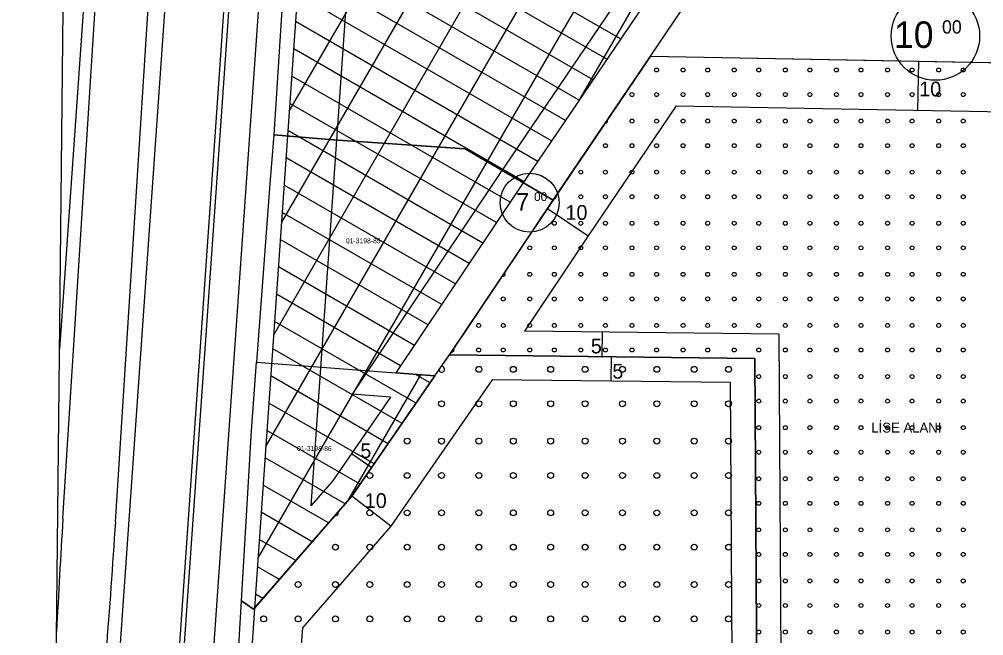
# Model space of a CAD drawing. Extents: x 419396 to 421519, y 4453567 to 4456767.
# Drawn here: x 420195.1 to 420391.3, y 4455033.3 to 4455158.8 of the extents above; entities that cross this region are included whole.
import ezdxf

# ---------------------------------------------------------------- set-up
doc = ezdxf.new("R2010")
doc.units = 0
for name, color, linetype in [('0_KADASTRO', 7, 'Continuous'), ('@PL', 7, 'Continuous'), ('ADAKENARI1000', 7, 'Continuous'), ('DEGISIKLIK_PARSELNO', 7, 'Continuous'), ('F_YAPI_YAKLAŞMA', 7, 'Continuous'), ('FAT_RAYLıSISTEM', 7, 'Continuous'), ('KALDIRIM', 7, 'Continuous'), ('Level 35', 7, 'Continuous'), ('Level 43', 7, 'Continuous'), ('Y_Lejant', 7, 'Continuous')]:
    doc.layers.add(name, color=color, linetype=linetype)

msp = doc.modelspace()

# ---------------------------------------------------------------- linework, layer by layer
at = {"layer": '0_KADASTRO'}
for p, q in [((420323.5, 4455151.27), (420340.02, 4455175.71)), ((420246.85, 4455135.3), (420246.05, 4455125.31)), ((420285.83, 4455132.45), (420303.7, 4455121.98)), ((420246.05, 4455125.31), (420243.35, 4455089.04)), ((420300.77, 4455117.6), (420300.9, 4455117.8)), ((420279.66, 4455086.21), (420282.64, 4455090.54)), ((420243.35, 4455089.04), (420279.66, 4455086.21))]:
    msp.add_line(p, q, dxfattribs=at)
for points in [[(420293.99, 4455228.12), (420291.73, 4455205.79), (420252.3, 4455209.37), (420248.66, 4455162.87), (420246.85, 4455135.3)], [(420303.7, 4455121.98), (420304.63, 4455123.36), (420323.5, 4455151.27)], [(420246.85, 4455135.3), (420255.73, 4455134.55), (420259.96, 4455134.2), (420274.95, 4455133.19), (420285.83, 4455132.45)], [(420274.95, 4455133.19), (420259.96, 4455134.2), (420255.73, 4455134.55), (420246.85, 4455135.3)], [(420300.9, 4455117.8), (420302.55, 4455120.28), (420303.7, 4455121.98), (420285.83, 4455132.45), (420274.95, 4455133.19)], [(420282.64, 4455090.54), (420297, 4455111.92), (420298.13, 4455113.63), (420300.77, 4455117.6)]]:
    msp.add_lwpolyline(points, dxfattribs=at)
for points in [[(420282.64, 4455090.54), (420297, 4455111.92), (420302.55, 4455120.28), (420304.63, 4455123.36), (420323.5, 4455151.27), (420436.44, 4455149.21), (420436.45, 4455145.33), (420439.36, 4455123.19), (420445.76, 4455074.56), (420468.34, 4454994.88), (420469.12, 4454986.67), (420468.62, 4454979.78), (420466.97, 4454973.08), (420464.21, 4454966.74), (420458.28, 4454957.65), (420451.94, 4454952.12), (420444.92, 4454948.04), (420432.46, 4454945.39), (420391.72, 4454939.02), (420368.62, 4454935.68), (420345.72, 4454934.33), (420344.76, 4455089.79)], [(420235.11, 4454952.64), (420240.31, 4455040.41), (420242.76, 4455038.75), (420262.76, 4455061.76), (420279.66, 4455086.21), (420281.91, 4455089.46), (420282.64, 4455090.54), (420344.76, 4455089.79), (420345.72, 4454934.33), (420272.67, 4454930.03), (420267.59, 4454930.12), (420261.9, 4454931.28), (420257.42, 4454932.55), (420253.39, 4454934.03), (420249.93, 4454935.75), (420245.65, 4454938.18), (420242, 4454941), (420237.77, 4454944.85), (420235.41, 4454949.09)], [(420240.31, 4455040.41), (420242.31, 4455075.03), (420243.35, 4455089.04), (420279.66, 4455086.21), (420262.76, 4455061.76), (420242.76, 4455038.75)]]:
    msp.add_lwpolyline(points, close=True, dxfattribs=at)
at = {"layer": '@PL'}
for centre, radius in [((420381.48, 4455155.39), 9), ((420298.93, 4455121.46), 6)]:
    msp.add_circle(centre, radius, dxfattribs=at)
at = {"layer": 'ADAKENARI1000'}
for p, q in [((420265.69, 4455363.64), (420242.95, 4455038.97)), ((420323.63, 4455163.96), (420296.75, 4455124.2)), ((420323.5, 4455151.27), (420302.56, 4455120.29)), ((420323.5, 4455151.27), (420436.44, 4455149.21)), ((420296.75, 4455124.2), (420271.71, 4455086.83)), ((420302.56, 4455120.29), (420282.62, 4455090.54)), ((420279.66, 4455086.21), (420282.62, 4455090.54)), ((420344.76, 4455089.79), (420282.62, 4455090.54)), ((420345.72, 4454934.33), (420344.76, 4455089.79)), ((420279.66, 4455086.21), (420271.71, 4455086.83)), ((420279.66, 4455086.21), (420262.76, 4455061.76)), ((420262.76, 4455061.76), (420242.95, 4455038.97)), ((420242.95, 4455038.97), (420241.29, 4455015.25))]:
    msp.add_line(p, q, dxfattribs=at)
at = {"layer": 'F_YAPI_YAKLAŞMA'}
for p, q in [((420318.89, 4455165.89), (420292.6, 4455126.99)), ((420377.94, 4455140.27), (420378.13, 4455150.27)), ((420328.74, 4455141.17), (420310.86, 4455114.71)), ((420328.74, 4455141.17), (420427.14, 4455139.38)), ((420292.6, 4455126.99), (420262.8, 4455082.51)), ((420302.56, 4455120.29), (420310.87, 4455114.72)), ((420310.86, 4455114.71), (420297.89, 4455095.36)), ((420349.73, 4455094.73), (420297.89, 4455095.36)), ((420313.69, 4455090.17), (420313.75, 4455095.17)), ((420350.66, 4454944.64), (420349.73, 4455094.73)), ((420315.54, 4455085.15), (420315.6, 4455090.14)), ((420291.28, 4455085.44), (420270.67, 4455055.62)), ((420339.79, 4455084.85), (420291.28, 4455085.44)), ((420340.66, 4454944.05), (420339.79, 4455084.85)), ((420270.6, 4455081.9), (420262.8, 4455082.51)), ((420270.6, 4455081.9), (420258.8, 4455064.83)), ((420262.69, 4455070.45), (420266.8, 4455067.61)), ((420258.8, 4455064.83), (420254.43, 4455059.8)), ((420270.67, 4455055.62), (420262.76, 4455061.76)), ((420270.67, 4455055.62), (420252.69, 4455034.93)), ((420252.69, 4455034.93), (420251.27, 4455014.64))]:
    msp.add_line(p, q, dxfattribs=at)
msp.add_lwpolyline([(420275.71, 4455363.6), (420254.43, 4455059.8)], dxfattribs=at)
at = {"layer": 'FAT_RAYLıSISTEM'}
for p, q in [((420214.7, 4455056.5), (420222.56, 4455180.73)), ((420203.96, 4455057.18), (420211.66, 4455178.85))]:
    msp.add_line(p, q, dxfattribs=at)
for centre, start, end in [((421800.78, 4454956.24), 176.38298, 177.20849), ((418617.89, 4455157.44), 354.48143, 356.38298)]:
    msp.add_arc(centre, 1600, start, end, dxfattribs=at)
at = {"layer": 'KALDIRIM'}
for p, q in [((420234.65, 4455539.59), (420203.28, 4455091.64)), ((420251.12, 4455538.54), (420214.59, 4455016.89)), ((420263.1, 4455537.78), (420226.57, 4455016.15)), ((420264.1, 4455537.72), (420227.56, 4455016.09)), ((420258.38, 4455370.29), (420233.55, 4455015.72))]:
    msp.add_line(p, q, dxfattribs=at)
at = {"layer": 'Level 35'}
for p, q in [((420250.03, 4455140.11), (420360.82, 4455331.99)), ((420248.44, 4455117.35), (420370.12, 4455328.11)), ((420246.85, 4455094.59), (420340.18, 4455256.25)), ((420245.25, 4455071.83), (420334.89, 4455227.09)), ((420243.66, 4455049.07), (420329.73, 4455198.15)), ((420317.44, 4455154.81), (420253.64, 4455191.64)), ((420314.64, 4455150.66), (420253.25, 4455186.09)), ((420311.83, 4455146.5), (420252.87, 4455180.55)), ((420309.02, 4455142.35), (420252.48, 4455175)), ((420306.21, 4455138.2), (420252.09, 4455169.45)), ((420309.3, 4455142.77), (420324.57, 4455169.2)), ((420303.41, 4455134.04), (420251.7, 4455163.9)), ((420300.6, 4455129.89), (420251.31, 4455158.35)), ((420297.79, 4455125.74), (420250.92, 4455152.8)), ((420295, 4455121.58), (420250.53, 4455147.25)), ((420292.21, 4455117.42), (420250.14, 4455141.7)), ((420289.42, 4455113.25), (420249.76, 4455136.15)), ((420286.63, 4455109.09), (420249.37, 4455130.6)), ((420283.84, 4455104.93), (420248.98, 4455125.05)), ((420281.05, 4455100.77), (420248.59, 4455119.51)), ((420278.26, 4455096.6), (420248.2, 4455113.96)), ((420275.47, 4455092.44), (420247.81, 4455108.41)), ((420272.68, 4455088.28), (420247.42, 4455102.86)), ((420275.84, 4455080.68), (420247.04, 4455097.31)), ((420272.99, 4455076.55), (420246.65, 4455091.76)), ((420262.08, 4455060.98), (420276.78, 4455086.43)), ((420278.69, 4455084.81), (420275.73, 4455086.52)), ((420270.13, 4455072.43), (420246.26, 4455086.21)), ((420267.28, 4455068.3), (420245.87, 4455080.66)), ((420264.43, 4455064.17), (420245.48, 4455075.11)), ((420261.37, 4455060.16), (420245.09, 4455069.56)), ((420258.03, 4455056.32), (420244.7, 4455064.01)), ((420254.69, 4455052.48), (420244.32, 4455058.46)), ((420251.35, 4455048.63), (420243.93, 4455052.92)), ((420248.01, 4455044.79), (420243.54, 4455047.37)), ((420244.67, 4455040.94), (420243.15, 4455041.82))]:
    msp.add_line(p, q, dxfattribs=at)
at = {"layer": 'Level 43'}
for centre, radius in [((420324.75, 4455148.49), 0.4), ((420330.15, 4455148.49), 0.4), ((420335.15, 4455148.49), 0.4), ((420340.55, 4455148.49), 0.4), ((420345.55, 4455148.49), 0.4), ((420350.95, 4455148.49), 0.4), ((420355.95, 4455148.49), 0.4), ((420361.35, 4455148.49), 0.4), ((420366.35, 4455148.49), 0.4), ((420371.75, 4455148.49), 0.4), ((420376.75, 4455148.49), 0.4), ((420382.15, 4455148.49), 0.4), ((420387.15, 4455148.49), 0.4), ((420319.75, 4455143.49), 0.4), ((420324.75, 4455143.49), 0.4), ((420330.15, 4455143.49), 0.4), ((420335.15, 4455143.49), 0.4), ((420340.55, 4455143.49), 0.4), ((420345.55, 4455143.49), 0.4), ((420350.95, 4455143.49), 0.4), ((420355.95, 4455143.49), 0.4), ((420361.35, 4455143.49), 0.4), ((420366.35, 4455143.49), 0.4), ((420371.75, 4455143.49), 0.4), ((420376.75, 4455143.49), 0.4), ((420382.15, 4455143.49), 0.4), ((420387.15, 4455143.49), 0.4), ((420319.75, 4455138.09), 0.4), ((420324.75, 4455138.09), 0.4), ((420330.15, 4455138.09), 0.4), ((420335.15, 4455138.09), 0.4), ((420340.55, 4455138.09), 0.4), ((420345.55, 4455138.09), 0.4), ((420350.95, 4455138.09), 0.4), ((420355.95, 4455138.09), 0.4), ((420361.35, 4455138.09), 0.4), ((420366.35, 4455138.09), 0.4), ((420371.75, 4455138.09), 0.4), ((420376.75, 4455138.09), 0.4), ((420382.15, 4455138.09), 0.4), ((420387.15, 4455138.09), 0.4), ((420314.35, 4455133.09), 0.4), ((420319.75, 4455133.09), 0.4), ((420324.75, 4455133.09), 0.4), ((420330.15, 4455133.09), 0.4), ((420335.15, 4455133.09), 0.4), ((420340.55, 4455133.09), 0.4), ((420345.55, 4455133.09), 0.4), ((420350.95, 4455133.09), 0.4), ((420355.95, 4455133.09), 0.4), ((420361.35, 4455133.09), 0.4), ((420366.35, 4455133.09), 0.4), ((420371.75, 4455133.09), 0.4), ((420376.75, 4455133.09), 0.4), ((420382.15, 4455133.09), 0.4), ((420387.15, 4455133.09), 0.4), ((420309.35, 4455127.69), 0.4), ((420314.35, 4455127.69), 0.4), ((420319.75, 4455127.69), 0.4), ((420324.75, 4455127.69), 0.4), ((420330.15, 4455127.69), 0.4), ((420335.15, 4455127.69), 0.4), ((420340.55, 4455127.69), 0.4), ((420345.55, 4455127.69), 0.4), ((420350.95, 4455127.69), 0.4), ((420355.95, 4455127.69), 0.4), ((420361.35, 4455127.69), 0.4), ((420366.35, 4455127.69), 0.4), ((420371.75, 4455127.69), 0.4), ((420376.75, 4455127.69), 0.4), ((420382.15, 4455127.69), 0.4), ((420387.15, 4455127.69), 0.4), ((420309.35, 4455122.69), 0.4), ((420314.35, 4455122.69), 0.4), ((420319.75, 4455122.69), 0.4), ((420324.75, 4455122.69), 0.4), ((420330.15, 4455122.69), 0.4), ((420335.15, 4455122.69), 0.4), ((420340.55, 4455122.69), 0.4), ((420345.55, 4455122.69), 0.4), ((420350.95, 4455122.69), 0.4), ((420355.95, 4455122.69), 0.4), ((420361.35, 4455122.69), 0.4), ((420366.35, 4455122.69), 0.4), ((420371.75, 4455122.69), 0.4), ((420376.75, 4455122.69), 0.4), ((420382.15, 4455122.69), 0.4), ((420387.15, 4455122.69), 0.4), ((420303.95, 4455117.29), 0.4), ((420309.35, 4455117.29), 0.4), ((420314.35, 4455117.29), 0.4), ((420319.75, 4455117.29), 0.4), ((420324.75, 4455117.29), 0.4), ((420330.15, 4455117.29), 0.4), ((420335.15, 4455117.29), 0.4), ((420340.55, 4455117.29), 0.4), ((420345.55, 4455117.29), 0.4), ((420350.95, 4455117.29), 0.4), ((420355.95, 4455117.29), 0.4), ((420361.35, 4455117.29), 0.4), ((420366.35, 4455117.29), 0.4), ((420371.75, 4455117.29), 0.4), ((420376.75, 4455117.29), 0.4), ((420382.15, 4455117.29), 0.4), ((420387.15, 4455117.29), 0.4), ((420298.95, 4455112.29), 0.4), ((420303.95, 4455112.29), 0.4), ((420309.35, 4455112.29), 0.4), ((420314.35, 4455112.29), 0.4), ((420319.75, 4455112.29), 0.4), ((420324.75, 4455112.29), 0.4), ((420330.15, 4455112.29), 0.4), ((420335.15, 4455112.29), 0.4), ((420340.55, 4455112.29), 0.4), ((420345.55, 4455112.29), 0.4), ((420350.95, 4455112.29), 0.4), ((420355.95, 4455112.29), 0.4), ((420361.35, 4455112.29), 0.4), ((420366.35, 4455112.29), 0.4), ((420371.75, 4455112.29), 0.4), ((420376.75, 4455112.29), 0.4), ((420382.15, 4455112.29), 0.4), ((420387.15, 4455112.29), 0.4), ((420298.95, 4455106.89), 0.4), ((420303.95, 4455106.89), 0.4), ((420309.35, 4455106.89), 0.4), ((420314.35, 4455106.89), 0.4), ((420319.75, 4455106.89), 0.4), ((420324.75, 4455106.89), 0.4), ((420330.15, 4455106.89), 0.4), ((420335.15, 4455106.89), 0.4), ((420340.55, 4455106.89), 0.4), ((420345.55, 4455106.89), 0.4), ((420350.95, 4455106.89), 0.4), ((420355.95, 4455106.89), 0.4), ((420361.35, 4455106.89), 0.4), ((420366.35, 4455106.89), 0.4), ((420371.75, 4455106.89), 0.4), ((420376.75, 4455106.89), 0.4), ((420382.15, 4455106.89), 0.4), ((420387.15, 4455106.89), 0.4), ((420293.55, 4455101.89), 0.4), ((420298.95, 4455101.89), 0.4), ((420303.95, 4455101.89), 0.4), ((420309.35, 4455101.89), 0.4), ((420314.35, 4455101.89), 0.4), ((420319.75, 4455101.89), 0.4), ((420324.75, 4455101.89), 0.4), ((420330.15, 4455101.89), 0.4), ((420335.15, 4455101.89), 0.4), ((420340.55, 4455101.89), 0.4), ((420345.55, 4455101.89), 0.4), ((420350.95, 4455101.89), 0.4), ((420355.95, 4455101.89), 0.4), ((420361.35, 4455101.89), 0.4), ((420366.35, 4455101.89), 0.4), ((420371.75, 4455101.89), 0.4), ((420376.75, 4455101.89), 0.4), ((420382.15, 4455101.89), 0.4), ((420387.15, 4455101.89), 0.4), ((420288.55, 4455096.49), 0.4), ((420293.55, 4455096.49), 0.4), ((420298.95, 4455096.49), 0.4), ((420303.95, 4455096.49), 0.4), ((420309.35, 4455096.49), 0.4), ((420314.35, 4455096.49), 0.4), ((420319.75, 4455096.49), 0.4), ((420324.75, 4455096.49), 0.4), ((420330.15, 4455096.49), 0.4), ((420335.15, 4455096.49), 0.4), ((420340.55, 4455096.49), 0.4), ((420345.55, 4455096.49), 0.4), ((420350.95, 4455096.49), 0.4), ((420355.95, 4455096.49), 0.4), ((420361.35, 4455096.49), 0.4), ((420366.35, 4455096.49), 0.4), ((420371.75, 4455096.49), 0.4), ((420376.75, 4455096.49), 0.4), ((420382.15, 4455096.49), 0.4), ((420387.15, 4455096.49), 0.4), ((420288.55, 4455091.49), 0.4), ((420293.55, 4455091.49), 0.4), ((420298.95, 4455091.49), 0.4), ((420303.95, 4455091.49), 0.4), ((420309.35, 4455091.49), 0.4), ((420314.35, 4455091.49), 0.4), ((420319.75, 4455091.49), 0.4), ((420324.75, 4455091.49), 0.4), ((420330.15, 4455091.49), 0.4), ((420335.15, 4455091.49), 0.4), ((420340.55, 4455091.49), 0.4), ((420345.55, 4455091.49), 0.4), ((420350.95, 4455091.49), 0.4), ((420355.95, 4455091.49), 0.4), ((420361.35, 4455091.49), 0.4), ((420366.35, 4455091.49), 0.4), ((420371.75, 4455091.49), 0.4), ((420376.75, 4455091.49), 0.4), ((420382.15, 4455091.49), 0.4), ((420387.15, 4455091.49), 0.4), ((420288.61, 4455087.56), 0.6), ((420295.61, 4455087.56), 0.6), ((420303.21, 4455087.56), 0.6), ((420310.21, 4455087.56), 0.6), ((420317.81, 4455087.56), 0.6), ((420324.81, 4455087.56), 0.6), ((420332.41, 4455087.56), 0.6), ((420339.41, 4455087.56), 0.6), ((420345.55, 4455086.09), 0.4), ((420350.95, 4455086.09), 0.4), ((420355.95, 4455086.09), 0.4), ((420361.35, 4455086.09), 0.4), ((420366.35, 4455086.09), 0.4), ((420371.75, 4455086.09), 0.4), ((420376.75, 4455086.09), 0.4), ((420382.15, 4455086.09), 0.4), ((420387.15, 4455086.09), 0.4), ((420281.01, 4455080.56), 0.6), ((420288.61, 4455080.56), 0.6), ((420295.61, 4455080.56), 0.6), ((420303.21, 4455080.56), 0.6), ((420310.21, 4455080.56), 0.6), ((420317.81, 4455080.56), 0.6), ((420324.81, 4455080.56), 0.6), ((420332.41, 4455080.56), 0.6), ((420339.41, 4455080.56), 0.6), ((420345.55, 4455081.09), 0.4), ((420350.95, 4455081.09), 0.4), ((420355.95, 4455081.09), 0.4), ((420361.35, 4455081.09), 0.4), ((420366.35, 4455081.09), 0.4), ((420371.75, 4455081.09), 0.4), ((420376.75, 4455081.09), 0.4), ((420382.15, 4455081.09), 0.4), ((420387.15, 4455081.09), 0.4), ((420345.55, 4455075.69), 0.4), ((420350.95, 4455075.69), 0.4), ((420355.95, 4455075.69), 0.4), ((420361.35, 4455075.69), 0.4), ((420366.35, 4455075.69), 0.4), ((420371.75, 4455075.69), 0.4), ((420376.75, 4455075.69), 0.4), ((420382.15, 4455075.69), 0.4), ((420387.15, 4455075.69), 0.4), ((420274.01, 4455072.96), 0.6), ((420281.01, 4455072.96), 0.6), ((420288.61, 4455072.96), 0.6), ((420295.61, 4455072.96), 0.6), ((420303.21, 4455072.96), 0.6), ((420310.21, 4455072.96), 0.6), ((420317.81, 4455072.96), 0.6), ((420324.81, 4455072.96), 0.6), ((420332.41, 4455072.96), 0.6), ((420339.41, 4455072.96), 0.6), ((420345.55, 4455070.69), 0.4), ((420350.95, 4455070.69), 0.4), ((420355.95, 4455070.69), 0.4), ((420361.35, 4455070.69), 0.4), ((420366.35, 4455070.69), 0.4), ((420371.75, 4455070.69), 0.4), ((420376.75, 4455070.69), 0.4), ((420382.15, 4455070.69), 0.4), ((420387.15, 4455070.69), 0.4), ((420266.41, 4455065.96), 0.6), ((420274.01, 4455065.96), 0.6), ((420281.01, 4455065.96), 0.6), ((420288.61, 4455065.96), 0.6), ((420295.61, 4455065.96), 0.6), ((420303.21, 4455065.96), 0.6), ((420310.21, 4455065.96), 0.6), ((420317.81, 4455065.96), 0.6), ((420324.81, 4455065.96), 0.6), ((420332.41, 4455065.96), 0.6), ((420339.41, 4455065.96), 0.6), ((420345.55, 4455065.29), 0.4), ((420350.95, 4455065.29), 0.4), ((420355.95, 4455065.29), 0.4), ((420361.35, 4455065.29), 0.4), ((420366.35, 4455065.29), 0.4), ((420371.75, 4455065.29), 0.4), ((420376.75, 4455065.29), 0.4), ((420382.15, 4455065.29), 0.4), ((420387.15, 4455065.29), 0.4), ((420266.41, 4455058.36), 0.6), ((420274.01, 4455058.36), 0.6), ((420281.01, 4455058.36), 0.6), ((420288.61, 4455058.36), 0.6), ((420295.61, 4455058.36), 0.6), ((420303.21, 4455058.36), 0.6), ((420310.21, 4455058.36), 0.6), ((420317.81, 4455058.36), 0.6), ((420324.81, 4455058.36), 0.6), ((420332.41, 4455058.36), 0.6), ((420339.41, 4455058.36), 0.6), ((420345.55, 4455060.29), 0.4), ((420350.95, 4455060.29), 0.4), ((420355.95, 4455060.29), 0.4), ((420361.35, 4455060.29), 0.4), ((420366.35, 4455060.29), 0.4), ((420371.75, 4455060.29), 0.4), ((420376.75, 4455060.29), 0.4), ((420382.15, 4455060.29), 0.4), ((420387.15, 4455060.29), 0.4), ((420345.55, 4455054.89), 0.4), ((420350.95, 4455054.89), 0.4), ((420355.95, 4455054.89), 0.4), ((420361.35, 4455054.89), 0.4), ((420366.35, 4455054.89), 0.4), ((420371.75, 4455054.89), 0.4), ((420376.75, 4455054.89), 0.4), ((420382.15, 4455054.89), 0.4), ((420387.15, 4455054.89), 0.4), ((420259.41, 4455051.36), 0.6), ((420266.41, 4455051.36), 0.6), ((420274.01, 4455051.36), 0.6), ((420281.01, 4455051.36), 0.6), ((420288.61, 4455051.36), 0.6), ((420295.61, 4455051.36), 0.6), ((420303.21, 4455051.36), 0.6), ((420310.21, 4455051.36), 0.6), ((420317.81, 4455051.36), 0.6), ((420324.81, 4455051.36), 0.6), ((420332.41, 4455051.36), 0.6), ((420339.41, 4455051.36), 0.6), ((420345.55, 4455049.89), 0.4), ((420350.95, 4455049.89), 0.4), ((420355.95, 4455049.89), 0.4), ((420361.35, 4455049.89), 0.4), ((420366.35, 4455049.89), 0.4), ((420371.75, 4455049.89), 0.4), ((420376.75, 4455049.89), 0.4), ((420382.15, 4455049.89), 0.4), ((420387.15, 4455049.89), 0.4), ((420251.81, 4455043.76), 0.6), ((420259.41, 4455043.76), 0.6), ((420266.41, 4455043.76), 0.6), ((420274.01, 4455043.76), 0.6), ((420281.01, 4455043.76), 0.6), ((420288.61, 4455043.76), 0.6), ((420295.61, 4455043.76), 0.6), ((420303.21, 4455043.76), 0.6), ((420310.21, 4455043.76), 0.6), ((420317.81, 4455043.76), 0.6), ((420324.81, 4455043.76), 0.6), ((420332.41, 4455043.76), 0.6), ((420339.41, 4455043.76), 0.6), ((420345.55, 4455044.49), 0.4), ((420350.95, 4455044.49), 0.4), ((420355.95, 4455044.49), 0.4), ((420361.35, 4455044.49), 0.4), ((420366.35, 4455044.49), 0.4), ((420371.75, 4455044.49), 0.4), ((420376.75, 4455044.49), 0.4), ((420382.15, 4455044.49), 0.4), ((420387.15, 4455044.49), 0.4), ((420345.55, 4455039.49), 0.4), ((420350.95, 4455039.49), 0.4), ((420355.95, 4455039.49), 0.4), ((420361.35, 4455039.49), 0.4), ((420366.35, 4455039.49), 0.4), ((420371.75, 4455039.49), 0.4), ((420376.75, 4455039.49), 0.4), ((420382.15, 4455039.49), 0.4), ((420387.15, 4455039.49), 0.4), ((420244.81, 4455036.76), 0.6), ((420251.81, 4455036.76), 0.6), ((420259.41, 4455036.76), 0.6), ((420266.41, 4455036.76), 0.6), ((420274.01, 4455036.76), 0.6), ((420281.01, 4455036.76), 0.6), ((420288.61, 4455036.76), 0.6), ((420295.61, 4455036.76), 0.6), ((420303.21, 4455036.76), 0.6), ((420310.21, 4455036.76), 0.6), ((420317.81, 4455036.76), 0.6), ((420324.81, 4455036.76), 0.6), ((420332.41, 4455036.76), 0.6), ((420339.41, 4455036.76), 0.6), ((420345.55, 4455034.09), 0.4), ((420350.95, 4455034.09), 0.4), ((420355.95, 4455034.09), 0.4), ((420361.35, 4455034.09), 0.4), ((420366.35, 4455034.09), 0.4), ((420371.75, 4455034.09), 0.4), ((420376.75, 4455034.09), 0.4), ((420382.15, 4455034.09), 0.4), ((420387.15, 4455034.09), 0.4)]:
    msp.add_circle(centre, radius, dxfattribs=at)
for centre, radius, start, end in [((420314.35, 4455138.09), 0.4, 264.8665, 27.0217), ((420303.95, 4455122.69), 0.4, 263.6118, 28.2764), ((420293.55, 4455106.89), 0.4, 238.8238, 53.5219), ((420283.15, 4455091.49), 0.4, 248.4398, 43.9059), ((420281.01, 4455087.56), 0.6, 199.6926, 91.548), ((420259.41, 4455058.36), 0.6, 258.7957, 19.2108)]:
    msp.add_arc(centre, radius, start, end, dxfattribs=at)
at = {"layer": 'Y_Lejant'}
msp.add_lwpolyline([(420209.76, 4455704.6), (421518.56, 4455690.86), (421518.56, 4454302.65), (420195.09, 4454316.54)], close=True, dxfattribs=at)

# ---------------------------------------------------------------- texts
at = {"layer": '0_KADASTRO'}
for s, p in [('01-3198-85', (420261.55, 4455113.22)), ('01-3198-86', (420251.6, 4455070.94))]:
    msp.add_text(s, height=1, dxfattribs=at).set_placement(p)
at = {"layer": '@PL'}
for s, height, p in [('10', 5.4, (420373.07, 4455152.98)), ('00', 2.7, (420382.83, 4455155.91)), ('7', 3.6, (420296.17, 4455119.86)), ('00', 1.8, (420299.83, 4455121.81))]:
    msp.add_text(s, height=height, dxfattribs=at).set_placement(p)
at = {"layer": 'DEGISIKLIK_PARSELNO'}
msp.add_text('LİSE ALANI', height=2, dxfattribs=at).set_placement((420368.44, 4455074.7))
at = {"layer": 'F_YAPI_YAKLAŞMA'}
for s, p in [('10', (420378.2, 4455143.11)), ('10', (420306.22, 4455117.99)), ('5', (420311.39, 4455090.81)), ('5', (420315.76, 4455085.67)), ('5', (420264.49, 4455069.48)), ('10', (420265.39, 4455059.34))]:
    msp.add_text(s, height=3, dxfattribs=at).set_placement(p)

doc.saveas('drawing.dxf')
